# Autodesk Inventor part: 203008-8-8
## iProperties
Category: Hydraulics
Company: Mountain Blue Industries Ltd.
Shininess: 64.0
Length Units: 11272
Angle Units: 11279
Time Units: 11290
Mass Units: 11286
Length Display Precision: 3
Angle Display Precision: 2
Compacted: True
Part Number: 203008-8-8
Document SubType Name: Modeling
Created: 2004-01
Designer: QBZ
Material: Steel, Mild
Manufacturer: Standard
Standards Organization: Custom
Description: #8 Bulkhead Run Tee
Catalog Web Link: http://www.aeroquip.com
Vendor: Aeroquip
Density: 0.0
Volumn: 0.0
Area: 0.0
PropertySet Name: Model Information
Control State: 0
Master: False
Checked Out: False
Length: 1
Author: QBZ
Revision Number: A
Title: JIC Bulkhead Male Run Tee
Subject: Hydraulic Adapters
Keywords: Couplings
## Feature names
1. Extrusion1
2. Extrusion2
3. Revolution1
4. Revolution2
5. Revolution3
6. Fillet1
7. Hole1
8. Hole2
